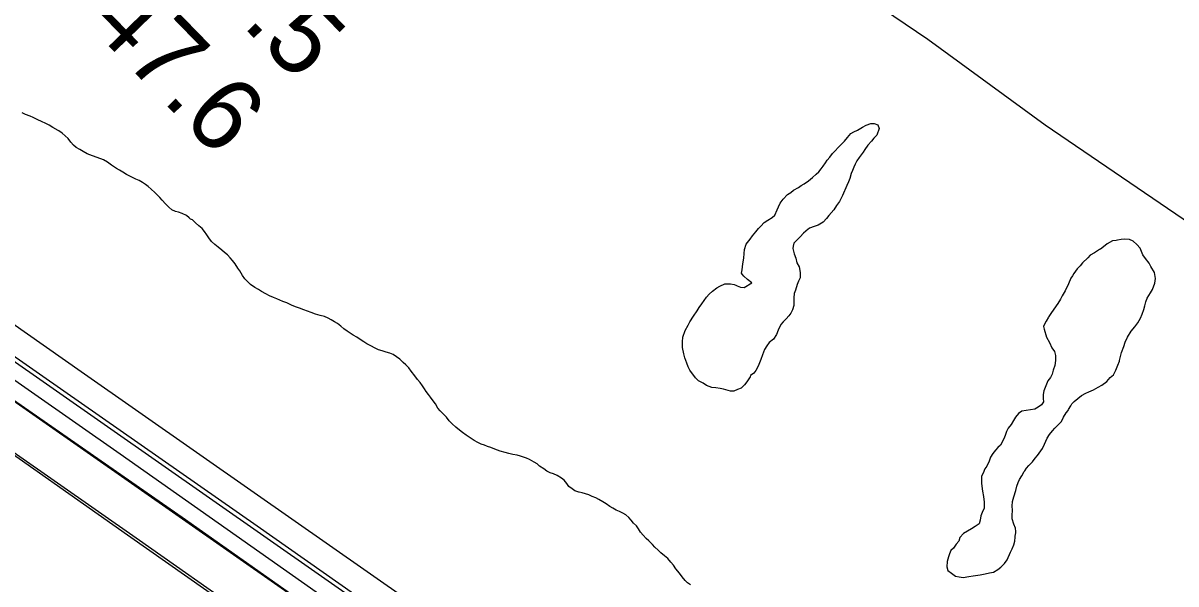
# Model space of a CAD drawing. Extents: x 3180038 to 3217926, y 922069 to 947485.
# Drawn here: x 3194087 to 3195138, y 939755 to 940267 of the extents above; entities that cross this region are included whole.
import ezdxf

# ---------------------------------------------------------------- set-up
doc = ezdxf.new("R2010")
doc.units = 0
for name, color, linetype in [('V-BRDG-OTLN', 7, 'Continuous'), ('V-FLOD-BASE', 7, 'Continuous'), ('V-RIVR-RANG', 7, 'Continuous'), ('V-RTRN-LOCK-CHMB', 7, 'Continuous'), ('V-SURV-LINE', 7, 'Continuous'), ('V-TOPO-SHOR', 7, 'Continuous')]:
    doc.layers.add(name, color=color, linetype=linetype)

msp = doc.modelspace()

# ---------------------------------------------------------------- linework, layer by layer
at = {"layer": 'V-BRDG-OTLN'}
for points in [[(3195422.5, 938982.5), (3195200.2, 939138.6), (3195015.1, 939266.9), (3194831.4, 939395.5), (3194650.2, 939522.3), (3194449.6, 939662.6), (3194232.3, 939815.9), (3194039.7, 939949.8), (3193833.3, 940094.1), (3193657.4, 940217.4), (3193675.9, 940244.6), (3193875.8, 940105.1), (3194105.5, 939944.6), (3194300.7, 939808.2), (3194538.1, 939641.4), (3194763.2, 939484.3), (3194963.5, 939343.7), (3195173.8, 939196.7), (3195355.6, 939069)], [(3193665.5, 940229.3), (3193899, 940067.3), (3194175.8, 939873.8), (3194519.6, 939631.7), (3194847, 939402.9), (3195103.1, 939224.1), (3195450.4, 938980), (3195744, 938774.1), (3195777.9, 938749.8), (3195986.7, 938605.7), (3196035.4, 938571.3), (3196263.1, 938411.8), (3196536.9, 938220.2)]]:
    msp.add_lwpolyline(points, dxfattribs=at)
at = {"layer": 'V-FLOD-BASE'}
msp.add_lwpolyline([(3193684.4, 940145.8), (3193688.9, 940145.8), (3193707.5, 940132.7), (3193772.4, 940087.2), (3193909, 939992.1), (3194043.6, 939897.8), (3194182.6, 939799.9), (3194341.4, 939688.4), (3194493.3, 939582.9), (3194680.8, 939451.8), (3194859.6, 939326.9), (3195022.8, 939212.2), (3195218.4, 939075.3), (3195421.9, 938933.2), (3195653.3, 938770.9), (3195881, 938611.7), (3195986.2, 938537.6)], dxfattribs=at)
at = {"layer": 'V-RTRN-LOCK-CHMB'}
msp.add_lwpolyline([(3195422.5, 938982.5), (3195200.2, 939138.6), (3195015.1, 939266.9), (3194831.4, 939395.5), (3194650.2, 939522.3), (3194449.6, 939662.6), (3194232.3, 939815.9), (3194039.7, 939949.8), (3193833.3, 940094.1), (3193657.4, 940217.4), (3193675.9, 940244.6), (3193688.2, 940263.7), (3193756.8, 940217.3), (3193944.5, 940086.3), (3194140.5, 939948.9), (3194298.1, 939838.5), (3194506.8, 939692.6), (3194707.4, 939552), (3194933.5, 939394.4), (3195147.3, 939244.4), (3195354.8, 939099.5)], dxfattribs=at)
at = {"layer": 'V-SURV-LINE'}
for points in [[(3193195.2, 940577), (3196532.4, 938242)], [(3196515.2, 938217.4), (3193178, 940552.4)]]:
    msp.add_lwpolyline(points, dxfattribs=at)
at = {"layer": 'V-TOPO-SHOR'}
for points in [[(3194736.8, 941489.4), (3194449.8, 940904.5), (3194360.3, 940725.4), (3194348.8, 940708.1), (3194345.9, 940673.5), (3194357.4, 940647.5), (3194380.5, 940618.6), (3194403.6, 940604.1), (3194455.6, 940560.8), (3194911.9, 940251.8), (3195018.8, 940173.8), (3195389.1, 939921.3)], [(3194114.5, 940171.4), (3194111.1, 940173.4), (3194107.6, 940175.2), (3194104.7, 940176.6), (3194100.4, 940178.7), (3194096.7, 940180.4), (3194093.8, 940181.5), (3194089.7, 940183.3), (3194086.6, 940184.8)], [(3194421.6, 939965.5), (3194418.4, 939966.5), (3194414.6, 939967.6), (3194411.2, 939968.8), (3194407.7, 939970.4), (3194404.9, 939971.9), (3194400.6, 939974), (3194397.9, 939975.9), (3194394.7, 939978.1), (3194391.5, 939980.2), (3194388.1, 939982.1), (3194385.4, 939983.9), (3194382.7, 939985.7), (3194379.8, 939987.8), (3194376.9, 939990.2), (3194373.8, 939992.5), (3194371.2, 939994.3), (3194368.3, 939995.9), (3194365.3, 939997.6), (3194362.1, 939998.9), (3194358.2, 940000), (3194354, 940001.2), (3194350, 940002.8), (3194346.5, 940003.8), (3194343.1, 940005), (3194339.4, 940006.5), (3194335.6, 940007.8), (3194331.9, 940009.4), (3194327.7, 940011.4), (3194324.2, 940012.7), (3194321.5, 940014), (3194318.6, 940015.1), (3194315.7, 940016.3), (3194312, 940017.8), (3194308.7, 940019.6), (3194304.8, 940021.7), (3194301.8, 940023.6), (3194298.6, 940025.4), (3194294.8, 940028.2), (3194291.9, 940030.8), (3194289.5, 940033.4), (3194287.4, 940036.3), (3194284.9, 940040.6), (3194283.1, 940043.2), (3194280.8, 940046.9), (3194278.2, 940050), (3194276, 940052.6), (3194273.7, 940055.2), (3194271, 940057.5), (3194268.6, 940059.4), (3194265.1, 940062.2), (3194262.2, 940064.6), (3194259.2, 940067.5), (3194256.7, 940070.6), (3194254.9, 940073.5), (3194252.7, 940076.4), (3194250.5, 940079.3), (3194247.6, 940081.8), (3194244.5, 940084.5), (3194241.8, 940087), (3194239.9, 940087.9), (3194238.9, 940088.9), (3194236.2, 940091.2), (3194232.5, 940093), (3194229.2, 940094), (3194226.3, 940094.8), (3194222.9, 940096.4), (3194220.4, 940098.7), (3194217.2, 940101.6), (3194214.3, 940105.2), (3194212.1, 940107.6), (3194209.8, 940109.7), (3194207.6, 940112), (3194204.1, 940115.1), (3194201.4, 940117.5), (3194199, 940119.5), (3194196.4, 940121.1), (3194193.1, 940123), (3194190.2, 940124.3), (3194184.7, 940127), (3194181.7, 940128.6), (3194178.2, 940130.7), (3194175.3, 940132.5), (3194172.6, 940133.8), (3194168.1, 940136.9), (3194164.4, 940139.8), (3194160.7, 940141.8), (3194155, 940144.1), (3194150.6, 940145.6), (3194146, 940147.4), (3194142.3, 940149.3), (3194139.1, 940151.3), (3194135.9, 940153.2), (3194133.3, 940155.3), (3194131.1, 940157.9), (3194128.4, 940161.2), (3194125.7, 940163.8), (3194123, 940166), (3194119.9, 940168.3), (3194119.5, 940168.6), (3194114.5, 940171.4)], [(3194751.3, 940029.8), (3194747.6, 940032.7), (3194744.2, 940035.9), (3194742.5, 940037.6), (3194741.9, 940038.4), (3194742.5, 940041.6), (3194743.1, 940047), (3194744, 940052.1), (3194744.3, 940056.4), (3194744.7, 940060.1), (3194746.4, 940065), (3194749.9, 940069.5), (3194751.9, 940072.7), (3194755.1, 940076.1), (3194757.4, 940079.2), (3194759.7, 940081.4), (3194762.8, 940084.8), (3194766, 940086.8), (3194770, 940089.4), (3194772.3, 940091.3), (3194774.6, 940096.2), (3194775.8, 940099), (3194777.3, 940102.2), (3194779.9, 940105.9), (3194783.9, 940110.1), (3194786.8, 940112.1), (3194789.3, 940114.1), (3194793.9, 940116.6), (3194796.5, 940118.3), (3194799.1, 940120), (3194803.1, 940122.8), (3194806.6, 940125.6), (3194810, 940128.8), (3194812.6, 940131), (3194814.6, 940133.6), (3194816.4, 940136.1), (3194818.4, 940139), (3194820.1, 940141.5), (3194822.4, 940144.4), (3194825, 940147.5), (3194827.3, 940150.1), (3194830.2, 940153.2), (3194833.4, 940156.3), (3194835.7, 940158.8), (3194838.6, 940162.3), (3194841.7, 940165.7), (3194844.3, 940167.3), (3194847.8, 940169), (3194852.1, 940171.6), (3194855.5, 940173.5), (3194859.8, 940174.9), (3194862.9, 940174.9), (3194866.1, 940173.8), (3194867.5, 940170.3), (3194865.2, 940164.3), (3194862.6, 940161.5), (3194860.3, 940158.9), (3194857.1, 940155.3), (3194854.5, 940151.3), (3194852.7, 940148.7), (3194849.3, 940143.9), (3194847, 940140.8), (3194845.5, 940137.9), (3194844.4, 940135.1), (3194843.2, 940132.2), (3194842, 940129.4), (3194840.6, 940124.8), (3194839.4, 940121.7), (3194837.9, 940118.5), (3194833.9, 940109.4), (3194831.3, 940104), (3194828.7, 940100.1), (3194826.1, 940096.4), (3194821.7, 940091), (3194819.4, 940088.4), (3194816.5, 940085), (3194811.7, 940082.2), (3194808.2, 940081.1), (3194803.9, 940079.4), (3194800.8, 940077.1), (3194800.5, 940076.8), (3194798.5, 940074.9), (3194795.3, 940071.7), (3194792.1, 940068.3), (3194789.8, 940065.8), (3194789.2, 940063.2), (3194788.9, 940060.9), (3194790, 940056.1), (3194791.4, 940052.1), (3194792.5, 940048.1), (3194794.5, 940044.3), (3194795.3, 940039.2), (3194795.3, 940034.3), (3194793.8, 940031.2), (3194792.7, 940028.1), (3194791.2, 940022.9), (3194790, 940020.1), (3194789.7, 940016.1), (3194789.7, 940009.2), (3194788.5, 940005.2), (3194786.8, 940002.1)], [(3193688.7, 940147.1), (3193722.9, 940123.8), (3193834.7, 940045.8), (3194003.3, 939927.9), (3194193.4, 939795.2), (3194383.7, 939661.4), (3194614.3, 939499.8), (3194866.5, 939323.6), (3195138.7, 939133.2), (3195411.1, 938942.1), (3195658.5, 938769.3), (3195876.5, 938617.4), (3195984.6, 938541.8)], [(3195084.7, 940068.6), (3195083.5, 940068.4), (3195080.1, 940068.1), (3195075.2, 940065.3), (3195071.8, 940062.5), (3195069.2, 940060.5), (3195068.3, 940060.2), (3195066.3, 940058.8), (3195063.7, 940057.1), (3195059.7, 940054.8), (3195057.4, 940052.6), (3195052.8, 940048), (3195050.5, 940045.2), (3195047.9, 940042.4), (3195044.7, 940038.1), (3195043.6, 940036.1), (3195042.1, 940034.1), (3195039.8, 940028.7), (3195036.9, 940022.5), (3195034.3, 940017.9), (3195032.5, 940014.8), (3195030.2, 940010.8), (3195024.4, 940002.6), (3195022.1, 939998.9), (3195021.6, 939998.3), (3195019.5, 939994.9), (3195017.8, 939991.5), (3195017.2, 939990), (3195017.8, 939987.5), (3195020, 939980.3), (3195022.5, 939975.4), (3195024.8, 939970.6), (3195027.3, 939967.1), (3195028.1, 939963.4), (3195028.1, 939958.8), (3195027.5, 939954.3), (3195026, 939950), (3195024.9, 939946.6), (3195023.4, 939943.4), (3195021.1, 939940.3), (3195017.3, 939931.2)], [(3195031.1, 939900.8), (3195033.4, 939903.4), (3195035.4, 939907.3), (3195037.7, 939911.3), (3195039.5, 939913.3), (3195040, 939914.2), (3195042.1, 939917.6), (3195042.9, 939919.3), (3195045, 939921.6), (3195048.4, 939924.4), (3195051.9, 939926.9), (3195055.6, 939929.2), (3195058.5, 939930.3), (3195062.8, 939932.3), (3195067.1, 939934.5), (3195070.2, 939936.5), (3195074.8, 939939.9), (3195078, 939943.3), (3195080.9, 939945.8), (3195082.9, 939950.1), (3195084.9, 939954.7), (3195086.4, 939958.4), (3195086.4, 939958.9), (3195087, 939961.5), (3195088.2, 939966.1), (3195090.2, 939971.8), (3195091.4, 939975.5), (3195093.7, 939980.3), (3195096.9, 939985.7), (3195100.3, 939989.7), (3195102.1, 939992), (3195103.2, 939993.4), (3195105.5, 939997.4), (3195107, 940001.1), (3195108.5, 940005.3), (3195109.6, 940008.7), (3195110.5, 940012.5), (3195111.7, 940015.6), (3195114.6, 940020.7), (3195116.6, 940023.5), (3195118.6, 940029.5), (3195119.2, 940033.8), (3195118.4, 940039.2), (3195114.8, 940044.7), (3195114.2, 940045.9), (3195113.4, 940047.6), (3195110, 940051.9), (3195107.7, 940055.3), (3195106.3, 940058.2), (3195105.2, 940061.3), (3195102.3, 940064.8), (3195098.9, 940067.7), (3195095.5, 940069.1), (3195091.2, 940069.5), (3195087.8, 940069.2), (3195084.7, 940068.6)], [(3194786.8, 940002.1), (3194785, 939999.6), (3194782.7, 939997), (3194780.1, 939994.2), (3194777.8, 939991.6), (3194775.5, 939986.5), (3194774, 939982.5), (3194771.2, 939978.5), (3194767.1, 939975.4), (3194765.1, 939972.3), (3194763.1, 939968.9), (3194761, 939964), (3194759.6, 939959.8), (3194757.3, 939953.8), (3194755.2, 939949.8), (3194753.2, 939947.5), (3194750.3, 939945.3), (3194749.8, 939944.1), (3194748.6, 939942.1), (3194746.9, 939939.6), (3194744.8, 939936.7), (3194741.7, 939933.6), (3194738.5, 939932.5), (3194735.1, 939931.1), (3194731.9, 939931.1), (3194725.7, 939932.9), (3194722.5, 939933.5), (3194718.5, 939934.1), (3194715.1, 939934.4), (3194710, 939936.1), (3194707.1, 939938.2), (3194702.9, 939940.5), (3194700, 939943.1), (3194695, 939950), (3194693.3, 939953.1), (3194692.1, 939956.6), (3194690.5, 939961.4), (3194689.6, 939964.9), (3194688.3, 939970.9), (3194688.3, 939976), (3194688.6, 939980.3), (3194690.7, 939986.3), (3194693.3, 939991.1), (3194695, 939994.2), (3194698.2, 939999.4), (3194701.7, 940004.2), (3194703.4, 940007.3), (3194706, 940010.7), (3194710, 940016.7), (3194712.6, 940019.5), (3194715.5, 940022.1), (3194719.5, 940025.2), (3194722.4, 940026.6), (3194726.7, 940028.9), (3194732.1, 940028.8), (3194735.3, 940028.2), (3194736.7, 940027.6), (3194738.1, 940027.1), (3194741.2, 940025.9), (3194744.4, 940025.6), (3194751.3, 940029.8)], [(3194695.4, 939754.3), (3194692.9, 939756.3), (3194690.8, 939758.5), (3194687.9, 939761.6), (3194685.5, 939765.2), (3194682.3, 939769), (3194680, 939772.3), (3194677.6, 939775.2), (3194674.9, 939778.3), (3194671.8, 939781), (3194668.6, 939783.6), (3194666.1, 939786.1), (3194663, 939788.8), (3194660.8, 939791.1), (3194657.5, 939794.6), (3194655.2, 939796.8), (3194652.4, 939799.8), (3194650.1, 939802.4), (3194648.1, 939805.5), (3194646.2, 939808.1), (3194643.6, 939810.8), (3194641.4, 939813.4), (3194639.3, 939815.8), (3194636.7, 939818.3), (3194634, 939819.9), (3194630.8, 939821.4), (3194627.8, 939822.4), (3194624.7, 939824.2), (3194622, 939826), (3194618.7, 939828.2), (3194615.6, 939830), (3194611.9, 939832.3), (3194609.2, 939833.6), (3194605.8, 939835.1), (3194602.8, 939836.4), (3194599.9, 939837.4), (3194596.7, 939838.2), (3194594.1, 939839), (3194593.8, 939839), (3194590.1, 939840.2), (3194587.6, 939842), (3194584.8, 939844.2), (3194582.9, 939846.7), (3194580.5, 939849.7), (3194578, 939851.7), (3194574, 939854), (3194570.6, 939855.5), (3194567.7, 939856.6), (3194564.7, 939858.2), (3194562, 939860.2), (3194558.1, 939862.6), (3194555.7, 939864.6), (3194553.2, 939866.4), (3194548.7, 939868.6), (3194546, 939870), (3194540.8, 939871.8), (3194537.5, 939872.6), (3194533.6, 939873.3), (3194529.9, 939874.1), (3194526.6, 939875.1), (3194522.2, 939876.4), (3194517.4, 939878.1), (3194513.6, 939879.5), (3194510.7, 939880.5), (3194507.8, 939881.7), (3194504.9, 939882.8), (3194501.7, 939884.3), (3194498.5, 939885.9), (3194493.9, 939889), (3194491.1, 939890.8), (3194487.8, 939893.2), (3194485.1, 939895.3), (3194481.7, 939898.3), (3194478.5, 939901.3), (3194475.8, 939903.9), (3194473.1, 939907.2), (3194470.1, 939910.3), (3194467.4, 939913), (3194465.3, 939915.4), (3194463.1, 939919.3), (3194461.2, 939922.1), (3194458.8, 939925.5), (3194456.9, 939927.9), (3194454.8, 939930.6), (3194453.2, 939933.2), (3194451.5, 939935.8), (3194449.1, 939938.9), (3194446.7, 939941.6), (3194444.3, 939945), (3194441.1, 939949.2), (3194439, 939952.1), (3194436.8, 939954.4), (3194436.3, 939954.9), (3194433.8, 939957.2), (3194430.6, 939960.1), (3194427.7, 939962.4), (3194424.7, 939964.3), (3194421.6, 939965.5)], [(3195017.3, 939931.2), (3195016.7, 939927.8), (3195016.7, 939924.3), (3195017, 939921.2), (3195015.2, 939918.6), (3195012.4, 939916.4), (3195009.2, 939914.7), (3195005.2, 939913.9), (3194997.5, 939912.8), (3194994.3, 939910.5), (3194991.7, 939907.4), (3194989.7, 939904.3), (3194987.7, 939900.6), (3194985.1, 939897.2), (3194983.3, 939894.3), (3194982.2, 939890.6), (3194981, 939887.5), (3194978.1, 939881.8), (3194975.5, 939879.5), (3194973.5, 939877.3), (3194970.9, 939874.1), (3194968.9, 939870.7), (3194967.7, 939867.3), (3194965.4, 939862.7), (3194963.6, 939860.2), (3194962.2, 939856.2), (3194960.7, 939853.4), (3194960.7, 939849.9), (3194960.7, 939846.8), (3194961.5, 939839.9), (3194962.6, 939835.1), (3194963.1, 939829.9), (3194963.1, 939824.2), (3194961.3, 939820.5), (3194960.2, 939817.4), (3194959.3, 939813.4), (3194958.4, 939810), (3194955, 939807.7), (3194951.5, 939805.4), (3194947.8, 939803.5), (3194944.3, 939801.2), (3194940.9, 939797.5), (3194940, 939794.4), (3194937.7, 939791.5), (3194935.1, 939787.8), (3194932.8, 939785.6), (3194931.6, 939782.7), (3194930.5, 939779.9), (3194929.3, 939775.6), (3194929, 939770.8), (3194930.1, 939767.6), (3194933.2, 939765), (3194936.9, 939762.4), (3194940.3, 939761.8), (3194944, 939761.2), (3194949.2, 939762), (3194953.2, 939762.6), (3194959.5, 939763.7), (3194964, 939764.5), (3194968, 939765.3), (3194971.5, 939765.9), (3194975.5, 939768.4), (3194978.4, 939770.7), (3194981.5, 939773.8), (3194983.9, 939777.2), (3194987, 939784.3), (3194988.5, 939787.4), (3194990, 939790.9), (3194991.1, 939794.3), (3194991.4, 939798), (3194991.4, 939798.8), (3194991.8, 939801.7), (3194992, 939803.1), (3194991.5, 939806), (3194990.1, 939809.7), (3194988.7, 939814.6), (3194988.7, 939817.7), (3194988.8, 939822.6), (3194988.5, 939826.3), (3194988.8, 939830.3), (3194989.4, 939832.6), (3194990, 939834.6), (3194991.8, 939840.5), (3194992.7, 939844.3), (3194994.1, 939847.7), (3194995.3, 939850.5), (3194997.3, 939853.9), (3194999.6, 939857.9), (3195000.2, 939858.5), (3195001.6, 939860.8), (3195003.9, 939863.3), (3195007.1, 939866.7), (3195009.7, 939869.8), (3195011.7, 939872.4), (3195016.1, 939878.6), (3195018.1, 939882.6), (3195020.4, 939888), (3195022.7, 939891.4), (3195025.3, 939894.8), (3195027.6, 939897.4), (3195031.1, 939900.8)]]:
    msp.add_lwpolyline(points, dxfattribs=at)

# ---------------------------------------------------------------- texts
at = {"layer": 'V-RIVR-RANG'}
for s, p in [('48.5', (3194216.6, 940336.3)), ('47.6', (3194143.8, 940267.7))]:
    msp.add_text(s, height=67, rotation=314.2083, dxfattribs=at).set_placement(p)

doc.saveas('drawing.dxf')
